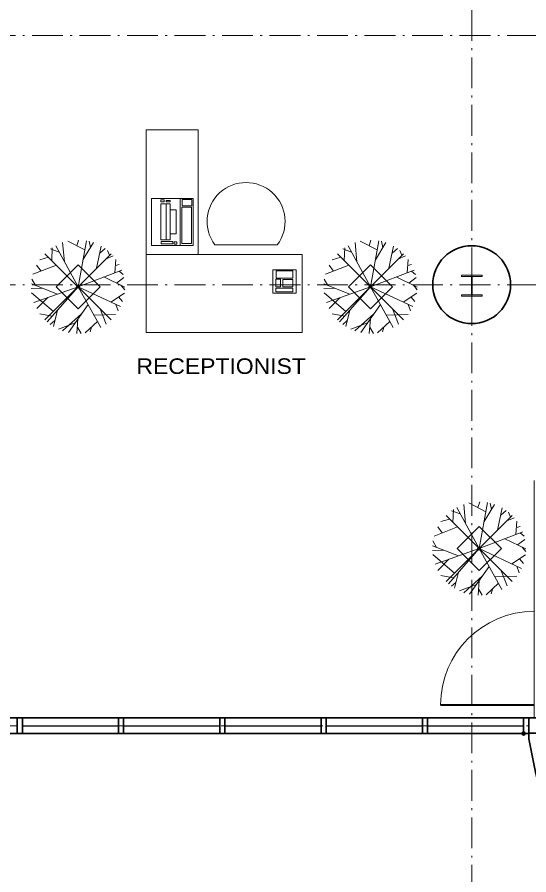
# Model space of a CAD drawing. Extents: x -118748 to -117136, y -118748 to -117596.
# Drawn here: x -118046.3 to -117888.7, y -118597 to -118332.8 of the extents above; entities that cross this region are included whole.
import ezdxf

# ---------------------------------------------------------------- set-up
doc = ezdxf.new("R2010")
doc.units = 0
doc.header["$LTSCALE"] = 1.9
doc.header["$PDMODE"] = 32
doc.header["$PDSIZE"] = 0.95
doc.linetypes.add('DOT_DASHED', pattern=[7.7, 5, -1.2, 0.3, -1.2])
doc.linetypes.add('MEDIUM_DASHED', pattern=[4.5, 3, -1.5])
for name, color, linetype, lineweight in [('10', 7, 'DOT_DASHED', 13), ('12', 7, 'Continuous', 13), ('15', 7, 'Continuous', 13), ('16', 7, 'Continuous', 13), ('2', 7, 'Continuous', 35), ('25', 7, 'Continuous', 13), ('3', 7, 'Continuous', 35), ('30', 7, 'Continuous', 13), ('4', 7, 'Continuous', 35), ('5', 7, 'Continuous', 13), ('6', 7, 'Continuous', 13), ('8', 7, 'MEDIUM_DASHED', 13), ('9', 7, 'Continuous', 35)]:
    doc.layers.add(name, color=color, linetype=linetype, lineweight=lineweight)
doc.layers.add('53', color=7, linetype='Continuous')

msp = doc.modelspace()

# ---------------------------------------------------------------- linework, layer by layer
at = {"layer": '10'}
for p, q in [((-117906.321, -117628.339), (-117906.321, -118698.41)), ((-118641.571, -118338.41), (-117285.521, -118338.41)), ((-118641.571, -118415.21), (-117285.521, -118415.21))]:
    msp.add_line(p, q, dxfattribs=at)
at = {"layer": '12'}
msp.add_lwpolyline([(-117909.504, -118418.762), (-117903.088, -118418.762), (-117903.088, -118418.366), (-117906.172, -118418.366), (-117906.172, -118412.662), (-117903.088, -118412.662), (-117903.088, -118412.266), (-117909.504, -118412.266), (-117909.504, -118412.662), (-117906.42, -118412.662), (-117906.42, -118418.366), (-117909.504, -118418.366)], close=True, dxfattribs=at)
at = {"layer": '12', "lineweight": 35}
msp.add_circle((-117906.321, -118415.21), 12, dxfattribs=at)
at = {"layer": '15'}
msp.add_line((-117966.199, -118402.937), (-117985.399, -118402.937), dxfattribs=at)
for points in [[(-117990.564, -118405.936), (-118006.564, -118405.936), (-118006.564, -118367.536), (-117990.564, -118367.536)], [(-117958.564, -118429.936), (-118006.564, -118429.936), (-118006.564, -118405.936), (-117958.564, -118405.936)]]:
    msp.add_lwpolyline(points, close=True, dxfattribs=at)
msp.add_arc((-117975.799, -118395.737), 12, 323.1301, 216.86989, dxfattribs=at)
at = {"layer": '16'}
msp.add_line((-117996.114, -118403.087), (-117996.114, -118388.687), dxfattribs=at)
for points in [[(-117992.114, -118403.087), (-118004.914, -118403.087), (-118004.914, -118388.687), (-117992.114, -118388.687)], [(-118002.016, -118389.69), (-118001.017, -118389.69), (-118001.017, -118389.107), (-118002.016, -118389.107)], [(-117995.484, -118390.938), (-117992.53, -118390.938), (-117992.53, -118388.941), (-117995.484, -118388.941)], [(-118000.435, -118401.423), (-118002.035, -118401.423), (-118002.035, -118390.314), (-118000.435, -118390.314)], [(-118000.435, -118389.69), (-117999.187, -118389.69), (-117999.187, -118389.274), (-118000.435, -118389.274)], [(-117999.228, -118401.423), (-118000.435, -118401.423), (-118000.435, -118390.314), (-117999.228, -118390.314)], [(-117995.567, -118402.546), (-117992.571, -118402.546), (-117992.571, -118391.354), (-117995.567, -118391.354)], [(-117997.356, -118399.509), (-117999.228, -118399.509), (-117999.228, -118392.186), (-117997.356, -118392.186)], [(-117998.396, -118402.629), (-118001.933, -118402.629), (-118001.933, -118401.922), (-117998.396, -118401.922)], [(-117997.148, -118402.713), (-117997.98, -118402.713), (-117997.98, -118402.047), (-117997.148, -118402.047)], [(-117960.407, -118417.784), (-117967.607, -118417.784), (-117967.607, -118410.584), (-117960.407, -118410.584)], [(-117966.573, -118413.165), (-117961.455, -118413.165), (-117961.455, -118410.959), (-117966.573, -118410.959)], [(-117966.656, -118415.827), (-117965.2, -118415.827), (-117965.2, -118413.539), (-117966.656, -118413.539)], [(-117964.534, -118415.911), (-117961.414, -118415.911), (-117961.414, -118413.622), (-117964.534, -118413.622)], [(-117961.414, -118416.327), (-117966.656, -118416.327), (-117966.656, -118417.409), (-117961.414, -118417.409)]]:
    msp.add_lwpolyline(points, close=True, dxfattribs=at)
at = {"layer": '2'}
msp.add_lwpolyline([(-117888.716, -118548.633), (-117888.716, -118553.358), (-117883.908, -118553.358), (-117883.908, -118548.633)], close=True, dxfattribs=at)
at = {"layer": '25', "lineweight": 40}
msp.add_line((-117915.908, -118544.633), (-117887.108, -118544.633), dxfattribs=at)
at = {"layer": '25'}
msp.add_arc((-117887.108, -118544.633), 28.8, 90.00001, 180, dxfattribs=at)
at = {"layer": '3'}
for points in [[(-118098.321, -117954.41), (-117829.521, -117954.41), (-117459.921, -117954.41), (-117459.921, -118170.41), (-117370.321, -118170.41), (-117370.321, -118352.81), (-117459.921, -118352.81), (-117459.921, -118645.61), (-117704.721, -118645.61), (-117704.721, -118592.81), (-117847.121, -118592.81), (-117850.321, -118592.801), (-117860.744, -118590.984), (-117862.249, -118590.443), (-117871.571, -118585.668), (-117872.847, -118584.703), (-117880.323, -118577.368), (-117881.254, -118576.067), (-117886.205, -118566.837), (-117886.706, -118565.318), (-117888.682, -118555.032), (-117888.707, -118553.433), (-117890.316, -118553.433)], [(-117890.316, -118553.433), (-118075.926, -118553.433), (-118077.534, -118553.433), (-118077.559, -118555.032), (-118079.538, -118565.426), (-118080.102, -118566.923), (-118085.022, -118576.169), (-118086.007, -118577.43), (-118093.457, -118584.791), (-118094.773, -118585.701), (-118104.079, -118590.508), (-118105.606, -118590.985), (-118115.921, -118592.801), (-118119.121, -118592.81), (-118261.521, -118592.81), (-118261.521, -118645.61), (-118506.321, -118645.61), (-118506.321, -118352.81), (-118595.921, -118352.81)]]:
    msp.add_lwpolyline(points, dxfattribs=at)
msp.add_point((-117890.316, -118553.433), dxfattribs=at)
at = {"layer": '30'}
for p, q in [((-118031.768, -118408.12), (-118032.308, -118402.247)), ((-118025.495, -118404.521), (-118030.697, -118401.789)), ((-118027.987, -118403.212), (-118027.395, -118401.447)), ((-118027.57, -118415.845), (-118024.975, -118401.681)), ((-118026.051, -118407.554), (-118022.817, -118402.253)), ((-118023.756, -118403.793), (-118024.167, -118401.853)), ((-117941.709, -118408.12), (-117942.249, -118402.247)), ((-117935.436, -118404.521), (-117940.638, -118401.789)), ((-117937.928, -118403.212), (-117937.336, -118401.447)), ((-117937.511, -118415.845), (-117934.916, -118401.681)), ((-117935.992, -118407.554), (-117932.758, -118402.253)), ((-117933.697, -118403.793), (-117934.108, -118401.853)), ((-118033.353, -118405.202), (-118036.036, -118404.196)), ((-118035.633, -118407.782), (-118035.487, -118403.817)), ((-118027.57, -118415.845), (-118034.445, -118403.192)), ((-118021.865, -118410.141), (-118020.429, -118403.341)), ((-118020.89, -118405.525), (-118019.225, -118404.111)), ((-118017.859, -118406.134), (-118018.516, -118404.648)), ((-117943.294, -118405.202), (-117945.976, -118404.196)), ((-117945.574, -118407.782), (-117945.428, -118403.817)), ((-117937.511, -118415.845), (-117944.386, -118403.192)), ((-117931.806, -118410.141), (-117930.37, -118403.341)), ((-117930.831, -118405.525), (-117929.165, -118404.111)), ((-117927.8, -118406.134), (-117928.457, -118404.648)), ((-118036.648, -118406.768), (-118039.33, -118407.534)), ((-118017.388, -118405.663), (-118037.753, -118426.028)), ((-118017.388, -118426.028), (-118037.753, -118405.663)), ((-118019.076, -118407.351), (-118016.748, -118406.347)), ((-118016.248, -118411.543), (-118015.904, -118407.404)), ((-117946.588, -118406.768), (-117949.271, -118407.534)), ((-117927.329, -118405.663), (-117947.694, -118426.028)), ((-117927.329, -118426.028), (-117947.694, -118405.663)), ((-117929.017, -118407.351), (-117926.688, -118406.347)), ((-117926.189, -118411.543), (-117925.845, -118407.404)), ((-118034.239, -118409.177), (-118041.451, -118412.013)), ((-118038.907, -118411.012), (-118040.315, -118409.143)), ((-118016.064, -118409.331), (-118014.88, -118409.039)), ((-117944.18, -118409.177), (-117951.392, -118412.013)), ((-117948.848, -118411.012), (-117950.256, -118409.143)), ((-117926.005, -118409.331), (-117924.821, -118409.039)), ((-118027.57, -118415.845), (-118014.109, -118410.731)), ((-118019.64, -118412.832), (-118013.171, -118415.947)), ((-118014.906, -118411.034), (-118013.68, -118412.048)), ((-117937.511, -118415.845), (-117924.05, -118410.731)), ((-117929.581, -118412.832), (-117923.111, -118415.947)), ((-117924.847, -118411.034), (-117923.621, -118412.048)), ((-118033.894, -118418.094), (-118041.945, -118414.991)), ((-118040.704, -118415.469), (-118041.772, -118413.466)), ((-118015.721, -118414.719), (-118013.446, -118413.041)), ((-118014.345, -118415.382), (-118013.201, -118416.783)), ((-117943.835, -118418.094), (-117951.886, -118414.991)), ((-117950.645, -118415.469), (-117951.713, -118413.466)), ((-117925.662, -118414.719), (-117923.387, -118413.041)), ((-117924.285, -118415.382), (-117923.142, -118416.783)), ((-118038.523, -118416.31), (-118041.96, -118416.4)), ((-118035.152, -118423.427), (-118041.852, -118417.688)), ((-118027.57, -118415.845), (-118041.138, -118420.67)), ((-118027.57, -118415.845), (-118037.046, -118426.689)), ((-118027.57, -118415.845), (-118020.525, -118428.404)), ((-118027.57, -118415.845), (-118014.538, -118421.971)), ((-118017.518, -118420.571), (-118013.307, -118417.824)), ((-117948.464, -118416.31), (-117951.901, -118416.4)), ((-117945.092, -118423.427), (-117951.793, -118417.688)), ((-117937.511, -118415.845), (-117951.079, -118420.67)), ((-117937.511, -118415.845), (-117946.986, -118426.689)), ((-117937.511, -118415.845), (-117930.466, -118428.404)), ((-117937.511, -118415.845), (-117924.479, -118421.971)), ((-117927.458, -118420.571), (-117923.248, -118417.824)), ((-118036.897, -118419.162), (-118040.303, -118422.571)), ((-118015.087, -118418.986), (-118013.909, -118420.399)), ((-117946.838, -118419.162), (-117950.244, -118422.571)), ((-117925.028, -118418.986), (-117923.85, -118420.399)), ((-118033.892, -118423.08), (-118035.161, -118428.083)), ((-118024.482, -118421.352), (-118030.557, -118429.932)), ((-118020.725, -118422.691), (-118018.902, -118427.344)), ((-118015.959, -118421.303), (-118015.24, -118423.284)), ((-117943.833, -118423.08), (-117945.101, -118428.083)), ((-117934.422, -118421.352), (-117940.498, -118429.932)), ((-117930.665, -118422.691), (-117928.843, -118427.344)), ((-117925.9, -118421.303), (-117925.181, -118423.284)), ((-118035.493, -118424.912), (-118039.343, -118424.138)), ((-118026.513, -118424.221), (-118032.322, -118429.439)), ((-118027.583, -118425.732), (-118027.909, -118430.242)), ((-118022.671, -118424.579), (-118015.986, -118424.399)), ((-117945.434, -118424.912), (-117949.284, -118424.138)), ((-117936.454, -118424.221), (-117942.263, -118429.439)), ((-117937.524, -118425.732), (-117937.85, -118430.242)), ((-117932.612, -118424.579), (-117925.927, -118424.399)), ((-118034.7, -118426.265), (-118036.115, -118427.436)), ((-118028.421, -118426.916), (-118033.62, -118428.913)), ((-118027.767, -118428.279), (-118026.579, -118430.211)), ((-118021.57, -118426.542), (-118025.361, -118430.075)), ((-118023.47, -118428.312), (-118023.871, -118429.762)), ((-117944.641, -118426.265), (-117946.056, -118427.436)), ((-117938.362, -118426.916), (-117943.561, -118428.913)), ((-117937.708, -118428.279), (-117936.52, -118430.211)), ((-117931.511, -118426.542), (-117935.302, -118430.075)), ((-117933.411, -118428.312), (-117933.812, -118429.762)), ((-117904.034, -118496.474), (-117910.908, -118483.821)), ((-117908.231, -118488.748), (-117908.772, -118482.876)), ((-117901.959, -118485.149), (-117907.16, -118482.418)), ((-117904.451, -118483.841), (-117903.859, -118482.075)), ((-117904.034, -118496.474), (-117901.438, -118482.31)), ((-117902.515, -118488.183), (-117899.28, -118482.881)), ((-117900.22, -118484.422), (-117900.63, -118482.482)), ((-117898.329, -118490.769), (-117896.892, -118483.97)), ((-117893.852, -118486.292), (-117914.216, -118506.657)), ((-117893.852, -118506.657), (-117914.216, -118486.292)), ((-117909.817, -118485.83), (-117912.499, -118484.825)), ((-117912.097, -118488.411), (-117911.95, -118484.446)), ((-117897.354, -118486.154), (-117895.688, -118484.739)), ((-117894.323, -118486.763), (-117894.979, -118485.277)), ((-117913.111, -118487.397), (-117915.793, -118488.163)), ((-117895.54, -118487.98), (-117893.211, -118486.976)), ((-117892.712, -118492.172), (-117892.367, -118488.033)), ((-117910.702, -118489.806), (-117917.914, -118492.642)), ((-117915.37, -118491.641), (-117916.779, -118489.772)), ((-117904.034, -118496.474), (-117890.573, -118491.36)), ((-117892.528, -118489.96), (-117891.344, -118489.668)), ((-117891.37, -118491.662), (-117890.144, -118492.677)), ((-117917.168, -118496.098), (-117918.236, -118494.094)), ((-117896.103, -118493.461), (-117889.634, -118496.575)), ((-117892.185, -118495.347), (-117889.91, -118493.67)), ((-117914.986, -118496.938), (-117918.423, -118497.029)), ((-117910.357, -118498.723), (-117918.408, -118495.62)), ((-117904.034, -118496.474), (-117917.602, -118501.298)), ((-117904.034, -118496.474), (-117913.509, -118507.318)), ((-117904.034, -118496.474), (-117896.989, -118509.033)), ((-117904.034, -118496.474), (-117891.002, -118502.6)), ((-117890.808, -118496.01), (-117889.664, -118497.412)), ((-117911.615, -118504.055), (-117918.315, -118498.317)), ((-117913.361, -118499.791), (-117916.767, -118503.2)), ((-117893.981, -118501.199), (-117889.77, -118498.453)), ((-117891.551, -118499.614), (-117890.373, -118501.028)), ((-117900.945, -118501.981), (-117907.02, -118510.561)), ((-117892.423, -118501.932), (-117891.704, -118503.913)), ((-117911.957, -118505.541), (-117915.807, -118504.766)), ((-117910.356, -118503.709), (-117911.624, -118508.712)), ((-117902.977, -118504.85), (-117908.785, -118510.068)), ((-117899.135, -118505.208), (-117892.449, -118505.028)), ((-117897.188, -118503.32), (-117895.366, -118507.973)), ((-117911.163, -118506.894), (-117912.579, -118508.065)), ((-117904.885, -118507.545), (-117910.083, -118509.542)), ((-117904.047, -118506.361), (-117904.372, -118510.87)), ((-117898.033, -118507.171), (-117901.825, -118510.704)), ((-117904.231, -118508.908), (-117903.042, -118510.84)), ((-117899.933, -118508.941), (-117900.335, -118510.391))]:
    msp.add_line(p, q, dxfattribs=at)
for points in [[(-118020.717, -118415.842), (-118027.506, -118422.63), (-118034.294, -118415.842), (-118027.506, -118409.054)], [(-117930.658, -118415.842), (-117937.447, -118422.63), (-117944.235, -118415.842), (-117937.447, -118409.054)], [(-117897.181, -118496.471), (-117903.969, -118503.259), (-117910.757, -118496.471), (-117903.969, -118489.683)]]:
    msp.add_lwpolyline(points, close=True, dxfattribs=at)
for p in [(-118027.57, -118415.845), (-117937.511, -118415.845), (-117904.034, -118496.474)]:
    msp.add_point(p, dxfattribs=at)
at = {"layer": '4'}
msp.add_lwpolyline([(-118496.721, -117964.01), (-118496.721, -118636.01), (-118271.121, -118636.01), (-118271.121, -118588.01), (-118115.969, -118588.01), (-118106.1, -118586.234), (-118096.66, -118581.314), (-118089.115, -118573.804), (-118084.156, -118564.399), (-118081.154, -118548.633), (-118079.134, -118548.633), (-117884.057, -118548.587), (-117881.646, -118565.336), (-117876.897, -118574.111), (-117869.271, -118581.538), (-117859.789, -118586.351), (-117850.271, -118588.01), (-117695.121, -118588.01), (-117695.121, -118636.01), (-117469.521, -118636.01), (-117469.521, -117964.01)], close=True, dxfattribs=at)
at = {"layer": '5'}
for points in [[(-117887.108, -118475.475), (-117887.108, -118548.633), (-118079.134, -118548.633), (-118079.133, -118475.475)], [(-117881.646, -118565.336), (-117884.057, -118548.587), (-118079.134, -118548.633), (-118081.154, -118548.633), (-118084.156, -118564.399)]]:
    msp.add_lwpolyline(points, dxfattribs=at)
at = {"layer": '6'}
msp.add_lwpolyline([(-117887.108, -118475.475), (-117887.108, -118548.633), (-118079.134, -118548.633), (-118079.134, -118475.475)], dxfattribs=at)
at = {"layer": '8'}
msp.add_line((-118077.526, -118551.033), (-117888.716, -118551.033), dxfattribs=at)
at = {"layer": '9', "lineweight": 13}
for p, q in [((-118075.926, -118548.633), (-117890.316, -118548.633)), ((-118075.926, -118553.433), (-117890.316, -118553.433))]:
    msp.add_line(p, q, dxfattribs=at)
at = {"layer": '9', "lineweight": 25}
for p, q in [((-118044.724, -118551.033), (-118015.123, -118551.033)), ((-118013.523, -118551.033), (-117983.921, -118551.033)), ((-117982.321, -118551.033), (-117952.719, -118551.033)), ((-117951.119, -118551.033), (-117921.518, -118551.033)), ((-117919.918, -118551.033), (-117890.316, -118551.033))]:
    msp.add_line(p, q, dxfattribs=at)
at = {"layer": '9'}
for points in [[(-118044.724, -118548.633), (-118046.324, -118548.633), (-118046.324, -118553.433), (-118044.724, -118553.433)], [(-118013.523, -118548.633), (-118015.123, -118548.633), (-118015.123, -118553.433), (-118013.523, -118553.433)], [(-117982.321, -118548.633), (-117983.921, -118548.633), (-117983.921, -118553.433), (-117982.321, -118553.433)], [(-117951.119, -118548.633), (-117952.719, -118548.633), (-117952.719, -118553.433), (-117951.119, -118553.433)], [(-117919.918, -118548.633), (-117921.518, -118548.633), (-117921.518, -118553.433), (-117919.918, -118553.433)], [(-117888.716, -118548.633), (-117890.316, -118548.633), (-117890.316, -118553.433), (-117888.716, -118553.433)]]:
    msp.add_lwpolyline(points, close=True, dxfattribs=at)

# ---------------------------------------------------------------- texts
at = {"layer": '53', "width": 1.1}
msp.add_text('RECEPTIONIST', height=4.8, dxfattribs=at).set_placement((-118009.572, -118442.695))

doc.saveas('drawing.dxf')
